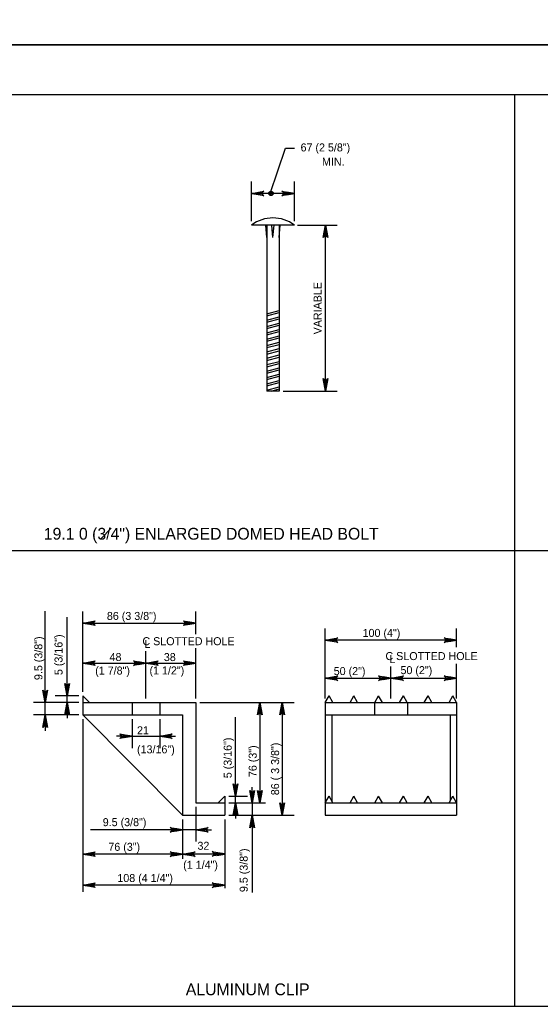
# Model space of a CAD drawing. Extents: x 0 to 36.3, y -66 to 0.
# Drawn here: x 17.21 to 25.01, y -58.48 to -43.62 of the extents above; entities that cross this region are included whole.
import ezdxf

# ---------------------------------------------------------------- set-up
doc = ezdxf.new("R2010")
doc.units = 0
for name, color, linetype in [('1', 7, 'Continuous'), ('3', 7, 'Continuous'), ('4', 7, 'Continuous'), ('5', 7, 'Continuous'), ('63', 7, 'Continuous'), ('8', 7, 'Continuous')]:
    doc.layers.add(name, color=color, linetype=linetype)

msp = doc.modelspace()

# ---------------------------------------------------------------- linework, layer by layer
at = {"layer": '1'}
msp.add_lwpolyline([(1.75, -65.25), (33.25, -65.25), (33.25, -44.75), (1.75, -44.75)], close=True, dxfattribs=at)
at = {"layer": '3'}
for p, q in [((24.625, -58.417), (24.625, -44.75)), ((20.961, -46.229), (21.191, -45.548)), ((21.191, -45.548), (21.325, -45.548)), ((21.369, -46.705), (21.966, -46.705)), ((21.789, -49.193), (21.789, -46.705)), ((21.154, -49.193), (21.966, -49.193)), ((18.423, -51.404), (18.575, -51.252)), ((1.75, -51.583), (32.25, -51.583)), ((21.786, -53.802), (21.786, -52.752)), ((23.754, -53.033), (23.754, -52.752)), ((23.754, -52.929), (21.786, -52.929)), ((21.786, -53.802), (21.786, -53.324)), ((22.77, -53.802), (22.77, -53.324)), ((23.754, -53.802), (23.754, -53.285)), ((23.754, -53.802), (23.754, -53.324)), ((21.786, -53.501), (22.77, -53.501)), ((22.77, -53.501), (23.754, -53.501)), ((18.151, -53.765), (18.25, -53.863)), ((18.151, -53.765), (18.151, -53.863)), ((21.786, -53.863), (21.843, -53.765)), ((21.9, -53.863), (21.843, -53.765)), ((22.157, -53.863), (22.214, -53.765)), ((22.27, -53.863), (22.214, -53.765)), ((22.528, -53.863), (22.585, -53.765)), ((22.642, -53.863), (22.585, -53.765)), ((22.899, -53.863), (22.956, -53.765)), ((23.012, -53.863), (22.956, -53.765)), ((23.27, -53.863), (23.327, -53.765)), ((23.383, -53.863), (23.327, -53.765)), ((23.641, -53.863), (23.698, -53.765)), ((23.754, -53.863), (23.698, -53.765)), ((18.151, -53.863), (19.844, -53.863)), ((18.151, -53.863), (18.151, -54.05)), ((19.844, -53.863), (19.844, -55.369)), ((21.786, -53.863), (21.786, -55.556)), ((21.786, -53.863), (23.754, -53.863)), ((23.754, -53.863), (23.754, -55.556)), ((19.647, -55.556), (18.151, -54.05)), ((21.786, -54.05), (23.754, -54.05)), ((21.884, -54.05), (21.884, -55.343)), ((23.656, -54.05), (23.656, -55.343)), ((18.889, -54.112), (18.889, -54.548)), ((19.303, -54.112), (19.303, -54.548)), ((18.771, -54.371), (18.653, -54.371)), ((18.889, -54.371), (19.303, -54.371)), ((19.421, -54.371), (19.539, -54.371)), ((19.844, -55.369), (20.277, -55.369)), ((20.277, -55.271), (20.179, -55.369)), ((20.277, -55.271), (20.277, -55.369)), ((20.277, -55.369), (20.277, -55.556)), ((21.786, -55.369), (21.843, -55.271)), ((21.786, -55.369), (23.754, -55.369)), ((21.9, -55.369), (21.843, -55.271)), ((22.157, -55.369), (22.214, -55.271)), ((22.27, -55.369), (22.214, -55.271)), ((22.528, -55.369), (22.585, -55.271)), ((22.642, -55.369), (22.585, -55.271)), ((22.899, -55.369), (22.956, -55.271)), ((23.012, -55.369), (22.956, -55.271)), ((23.27, -55.369), (23.327, -55.271)), ((23.383, -55.369), (23.327, -55.271)), ((23.641, -55.369), (23.698, -55.271)), ((23.754, -55.369), (23.698, -55.271)), ((19.647, -55.556), (20.277, -55.556)), ((21.786, -55.556), (23.754, -55.556)), ((1.75, -58.417), (32.25, -58.417))]:
    msp.add_line(p, q, dxfattribs=at)
for points in [[(21.789, -46.705), (21.824, -46.891), (21.814, -46.877), (21.801, -46.869), (21.789, -46.867), (21.776, -46.869), (21.764, -46.877), (21.754, -46.891), (21.789, -46.705), (21.764, -46.877), (21.776, -46.869), (21.789, -46.705), (21.789, -46.867), (21.801, -46.869), (21.789, -46.705), (21.814, -46.877)], [(21.789, -49.193), (21.754, -49.006), (21.764, -49.021), (21.776, -49.028), (21.789, -49.03), (21.801, -49.028), (21.814, -49.021), (21.824, -49.006), (21.789, -49.193), (21.814, -49.021), (21.801, -49.028), (21.789, -49.193), (21.789, -49.03), (21.776, -49.028), (21.789, -49.193), (21.764, -49.021)], [(21.786, -52.929), (21.972, -52.894), (21.958, -52.904), (21.951, -52.916), (21.948, -52.929), (21.951, -52.941), (21.958, -52.954), (21.972, -52.964), (21.786, -52.929), (21.958, -52.954), (21.951, -52.941), (21.786, -52.929), (21.948, -52.929), (21.951, -52.916), (21.786, -52.929), (21.958, -52.904)], [(23.754, -52.929), (23.568, -52.964), (23.582, -52.954), (23.59, -52.941), (23.592, -52.929), (23.59, -52.916), (23.582, -52.904), (23.568, -52.894), (23.754, -52.929), (23.582, -52.904), (23.59, -52.916), (23.754, -52.929), (23.592, -52.929), (23.59, -52.941), (23.754, -52.929), (23.582, -52.954)], [(21.786, -53.501), (21.972, -53.466), (21.958, -53.476), (21.951, -53.488), (21.948, -53.501), (21.951, -53.514), (21.958, -53.526), (21.972, -53.536), (21.786, -53.501), (21.958, -53.526), (21.951, -53.514), (21.786, -53.501), (21.948, -53.501), (21.951, -53.488), (21.786, -53.501), (21.958, -53.476)], [(22.77, -53.501), (22.584, -53.536), (22.598, -53.526), (22.605, -53.514), (22.608, -53.501), (22.605, -53.488), (22.598, -53.476), (22.584, -53.466), (22.77, -53.501), (22.598, -53.476), (22.605, -53.488), (22.77, -53.501), (22.608, -53.501), (22.605, -53.514), (22.77, -53.501), (22.598, -53.526)], [(22.77, -53.501), (22.957, -53.466), (22.942, -53.476), (22.935, -53.488), (22.933, -53.501), (22.935, -53.514), (22.942, -53.526), (22.957, -53.536), (22.77, -53.501), (22.942, -53.526), (22.935, -53.514), (22.77, -53.501), (22.933, -53.501), (22.935, -53.488), (22.77, -53.501), (22.942, -53.476)], [(23.754, -53.501), (23.568, -53.536), (23.582, -53.526), (23.59, -53.514), (23.592, -53.501), (23.59, -53.488), (23.582, -53.476), (23.568, -53.466), (23.754, -53.501), (23.582, -53.476), (23.59, -53.488), (23.754, -53.501), (23.592, -53.501), (23.59, -53.514), (23.754, -53.501), (23.582, -53.526)], [(18.889, -54.371), (18.703, -54.406), (18.717, -54.396), (18.725, -54.384), (18.727, -54.371), (18.725, -54.359), (18.717, -54.346), (18.703, -54.336), (18.889, -54.371), (18.717, -54.346), (18.725, -54.359), (18.889, -54.371), (18.727, -54.371), (18.725, -54.384), (18.889, -54.371), (18.717, -54.396)], [(19.303, -54.371), (19.489, -54.336), (19.475, -54.346), (19.467, -54.359), (19.465, -54.371), (19.467, -54.384), (19.475, -54.396), (19.489, -54.406), (19.303, -54.371), (19.475, -54.396), (19.467, -54.384), (19.303, -54.371), (19.465, -54.371), (19.467, -54.359), (19.303, -54.371), (19.475, -54.346)]]:
    msp.add_lwpolyline(points, dxfattribs=at)
for points in [[(21.808, -46.823), (21.769, -46.823), (21.789, -46.705)], [(21.808, -49.075), (21.769, -49.075), (21.789, -49.193)], [(21.904, -52.909), (21.904, -52.948), (21.786, -52.929)], [(23.636, -52.909), (23.636, -52.948), (23.754, -52.929)], [(21.904, -53.481), (21.904, -53.521), (21.786, -53.501)], [(22.652, -53.481), (22.652, -53.521), (22.77, -53.501)], [(22.888, -53.481), (22.888, -53.521), (22.77, -53.501)], [(23.636, -53.481), (23.636, -53.521), (23.754, -53.501)], [(18.771, -54.352), (18.771, -54.391), (18.889, -54.371)], [(19.421, -54.352), (19.421, -54.391), (19.303, -54.371)]]:
    msp.add_lwpolyline(points, close=True, dxfattribs=at)
for radius in [0.0333, 0.0167]:
    msp.add_circle((20.972, -46.229), radius, dxfattribs=at)
at = {"layer": '4'}
for p, q in [((20.678, -46.643), (20.678, -46.051)), ((21.323, -46.643), (21.323, -46.051)), ((21.205, -46.229), (20.796, -46.229)), ((21.323, -46.705), (20.678, -46.705)), ((20.908, -46.889), (20.892, -46.705)), ((20.908, -46.705), (20.908, -49.193)), ((21, -46.889), (20.984, -46.705)), ((21, -46.889), (21.017, -46.705)), ((21.093, -46.705), (21.093, -49.193)), ((21.093, -46.889), (21.109, -46.705)), ((21.093, -49.193), (20.908, -49.193)), ((21.093, -49.193), (21.093, -49.193)), ((17.588, -53.745), (17.588, -52.495)), ((18.151, -53.703), (18.151, -52.497)), ((19.844, -52.841), (19.844, -52.497)), ((17.914, -53.647), (17.914, -52.584)), ((18.269, -52.674), (19.726, -52.674)), ((18.151, -53.703), (18.151, -53.096)), ((19.096, -53.802), (19.096, -53.096)), ((19.844, -53.802), (19.844, -53.05)), ((19.844, -53.802), (19.844, -53.096)), ((18.269, -53.273), (18.978, -53.273)), ((19.214, -53.273), (19.726, -53.273)), ((18.09, -53.765), (17.737, -53.765)), ((17.914, -53.863), (17.914, -53.765)), ((18.09, -53.863), (17.411, -53.863)), ((17.588, -54.05), (17.588, -53.863)), ((18.09, -53.863), (17.733, -53.863)), ((18.09, -53.863), (17.737, -53.863)), ((19.905, -53.863), (21.318, -53.863)), ((19.905, -53.863), (20.982, -53.863)), ((20.805, -53.863), (20.805, -55.251)), ((21.141, -53.863), (21.141, -55.438)), ((18.09, -54.05), (17.411, -54.05)), ((17.914, -53.981), (17.914, -54.1)), ((17.588, -54.169), (17.588, -54.287)), ((18.151, -54.112), (18.151, -56.446)), ((18.151, -54.112), (18.151, -56.703)), ((20.439, -55.153), (20.439, -54.082)), ((20.691, -55.251), (20.691, -55.133)), ((20.339, -55.271), (20.617, -55.271)), ((20.339, -55.369), (20.617, -55.369)), ((20.339, -55.369), (20.868, -55.369)), ((20.339, -55.369), (20.887, -55.369)), ((20.439, -55.369), (20.439, -55.271)), ((20.691, -55.369), (20.691, -55.556)), ((19.844, -55.431), (19.844, -55.949)), ((20.439, -55.487), (20.439, -55.605)), ((19.647, -55.618), (19.647, -56.209)), ((19.647, -55.679), (19.647, -55.949)), ((20.277, -55.618), (20.277, -56.446)), ((20.277, -55.618), (20.277, -56.651)), ((20.339, -55.556), (20.868, -55.556)), ((20.339, -55.556), (20.375, -55.556)), ((20.546, -55.556), (21.318, -55.556)), ((20.691, -55.674), (20.691, -56.713)), ((19.529, -55.772), (18.266, -55.772)), ((19.844, -55.772), (19.647, -55.772)), ((19.962, -55.772), (20.08, -55.772)), ((19.529, -56.137), (18.269, -56.137)), ((20.159, -56.137), (19.765, -56.137)), ((20.159, -56.605), (18.269, -56.605))]:
    msp.add_line(p, q, dxfattribs=at)
for points in [[(20.678, -46.229), (20.865, -46.194), (20.85, -46.204), (20.843, -46.216), (20.841, -46.229), (20.843, -46.241), (20.85, -46.254), (20.865, -46.264), (20.678, -46.229), (20.85, -46.254), (20.843, -46.241), (20.678, -46.229), (20.841, -46.229), (20.843, -46.216), (20.678, -46.229), (20.85, -46.204)], [(21.323, -46.229), (21.136, -46.264), (21.151, -46.254), (21.158, -46.241), (21.16, -46.229), (21.158, -46.216), (21.151, -46.204), (21.136, -46.194), (21.323, -46.229), (21.151, -46.204), (21.158, -46.216), (21.323, -46.229), (21.16, -46.229), (21.158, -46.241), (21.323, -46.229), (21.151, -46.254)], [(18.151, -52.674), (18.337, -52.639), (18.323, -52.649), (18.316, -52.661), (18.314, -52.674), (18.316, -52.686), (18.323, -52.699), (18.337, -52.709), (18.151, -52.674), (18.323, -52.699), (18.316, -52.686), (18.151, -52.674), (18.314, -52.674), (18.316, -52.661), (18.151, -52.674), (18.323, -52.649)], [(19.844, -52.674), (19.658, -52.709), (19.672, -52.699), (19.679, -52.686), (19.681, -52.674), (19.679, -52.661), (19.672, -52.649), (19.658, -52.639), (19.844, -52.674), (19.672, -52.649), (19.679, -52.661), (19.844, -52.674), (19.681, -52.674), (19.679, -52.686), (19.844, -52.674), (19.672, -52.699)], [(18.151, -53.273), (18.337, -53.238), (18.323, -53.248), (18.316, -53.261), (18.314, -53.273), (18.316, -53.286), (18.323, -53.298), (18.337, -53.308), (18.151, -53.273), (18.323, -53.298), (18.316, -53.286), (18.151, -53.273), (18.314, -53.273), (18.316, -53.261), (18.151, -53.273), (18.323, -53.248)], [(19.096, -53.273), (18.91, -53.308), (18.924, -53.298), (18.931, -53.286), (18.933, -53.273), (18.931, -53.261), (18.924, -53.248), (18.91, -53.238), (19.096, -53.273), (18.924, -53.248), (18.931, -53.261), (19.096, -53.273), (18.933, -53.273), (18.931, -53.286), (19.096, -53.273), (18.924, -53.298)], [(19.096, -53.273), (19.282, -53.238), (19.268, -53.248), (19.261, -53.261), (19.258, -53.273), (19.261, -53.286), (19.268, -53.298), (19.282, -53.308), (19.096, -53.273), (19.268, -53.298), (19.261, -53.286), (19.096, -53.273), (19.258, -53.273), (19.261, -53.261), (19.096, -53.273), (19.268, -53.248)], [(19.844, -53.273), (19.658, -53.308), (19.672, -53.298), (19.679, -53.286), (19.681, -53.273), (19.679, -53.261), (19.672, -53.248), (19.658, -53.238), (19.844, -53.273), (19.672, -53.248), (19.679, -53.261), (19.844, -53.273), (19.681, -53.273), (19.679, -53.286), (19.844, -53.273), (19.672, -53.298)], [(17.914, -53.765), (17.879, -53.579), (17.889, -53.593), (17.902, -53.6), (17.914, -53.602), (17.927, -53.6), (17.939, -53.593), (17.949, -53.579), (17.914, -53.765), (17.939, -53.593), (17.927, -53.6), (17.914, -53.765), (17.914, -53.602), (17.902, -53.6), (17.914, -53.765), (17.889, -53.593)], [(17.588, -53.863), (17.553, -53.677), (17.563, -53.691), (17.576, -53.699), (17.588, -53.701), (17.601, -53.699), (17.613, -53.691), (17.623, -53.677), (17.588, -53.863), (17.613, -53.691), (17.601, -53.699), (17.588, -53.863), (17.588, -53.701), (17.576, -53.699), (17.588, -53.863), (17.563, -53.691)], [(17.914, -53.863), (17.949, -54.05), (17.939, -54.035), (17.927, -54.028), (17.914, -54.026), (17.902, -54.028), (17.889, -54.035), (17.879, -54.05), (17.914, -53.863), (17.889, -54.035), (17.902, -54.028), (17.914, -53.863), (17.914, -54.026), (17.927, -54.028), (17.914, -53.863), (17.939, -54.035)], [(20.805, -53.863), (20.84, -54.05), (20.83, -54.035), (20.817, -54.028), (20.805, -54.026), (20.793, -54.028), (20.78, -54.035), (20.77, -54.05), (20.805, -53.863), (20.78, -54.035), (20.793, -54.028), (20.805, -53.863), (20.805, -54.026), (20.817, -54.028), (20.805, -53.863), (20.83, -54.035)], [(21.141, -53.863), (21.176, -54.05), (21.166, -54.035), (21.154, -54.028), (21.141, -54.026), (21.129, -54.028), (21.116, -54.035), (21.106, -54.05), (21.141, -53.863), (21.116, -54.035), (21.129, -54.028), (21.141, -53.863), (21.141, -54.026), (21.154, -54.028), (21.141, -53.863), (21.166, -54.035)], [(17.588, -54.05), (17.623, -54.237), (17.613, -54.222), (17.601, -54.215), (17.588, -54.213), (17.576, -54.215), (17.563, -54.222), (17.553, -54.237), (17.588, -54.05), (17.563, -54.222), (17.576, -54.215), (17.588, -54.05), (17.588, -54.213), (17.601, -54.215), (17.588, -54.05), (17.613, -54.222)], [(20.439, -55.271), (20.404, -55.084), (20.414, -55.099), (20.427, -55.106), (20.439, -55.108), (20.452, -55.106), (20.464, -55.099), (20.474, -55.084), (20.439, -55.271), (20.464, -55.099), (20.452, -55.106), (20.439, -55.271), (20.439, -55.108), (20.427, -55.106), (20.439, -55.271), (20.414, -55.099)], [(20.691, -55.369), (20.656, -55.183), (20.666, -55.197), (20.678, -55.205), (20.691, -55.207), (20.703, -55.205), (20.716, -55.197), (20.726, -55.183), (20.691, -55.369), (20.716, -55.197), (20.703, -55.205), (20.691, -55.369), (20.691, -55.207), (20.678, -55.205), (20.691, -55.369), (20.666, -55.197)], [(20.805, -55.369), (20.77, -55.183), (20.78, -55.197), (20.793, -55.205), (20.805, -55.207), (20.817, -55.205), (20.83, -55.197), (20.84, -55.183), (20.805, -55.369), (20.83, -55.197), (20.817, -55.205), (20.805, -55.369), (20.805, -55.207), (20.793, -55.205), (20.805, -55.369), (20.78, -55.197)], [(20.439, -55.369), (20.474, -55.556), (20.464, -55.541), (20.452, -55.534), (20.439, -55.532), (20.427, -55.534), (20.414, -55.541), (20.404, -55.556), (20.439, -55.369), (20.414, -55.541), (20.427, -55.534), (20.439, -55.369), (20.439, -55.532), (20.452, -55.534), (20.439, -55.369), (20.464, -55.541)], [(21.141, -55.556), (21.106, -55.37), (21.116, -55.384), (21.129, -55.392), (21.141, -55.394), (21.154, -55.392), (21.166, -55.384), (21.176, -55.37), (21.141, -55.556), (21.166, -55.384), (21.154, -55.392), (21.141, -55.556), (21.141, -55.394), (21.129, -55.392), (21.141, -55.556), (21.116, -55.384)], [(20.691, -55.556), (20.726, -55.743), (20.716, -55.728), (20.703, -55.721), (20.691, -55.719), (20.678, -55.721), (20.666, -55.728), (20.656, -55.743), (20.691, -55.556), (20.666, -55.728), (20.678, -55.721), (20.691, -55.556), (20.691, -55.719), (20.703, -55.721), (20.691, -55.556), (20.716, -55.728)], [(19.647, -55.772), (19.461, -55.807), (19.475, -55.797), (19.482, -55.785), (19.485, -55.772), (19.482, -55.76), (19.475, -55.747), (19.461, -55.737), (19.647, -55.772), (19.475, -55.747), (19.482, -55.76), (19.647, -55.772), (19.485, -55.772), (19.482, -55.785), (19.647, -55.772), (19.475, -55.797)], [(19.844, -55.772), (20.03, -55.737), (20.016, -55.747), (20.009, -55.76), (20.006, -55.772), (20.009, -55.785), (20.016, -55.797), (20.03, -55.807), (19.844, -55.772), (20.016, -55.797), (20.009, -55.785), (19.844, -55.772), (20.006, -55.772), (20.009, -55.76), (19.844, -55.772), (20.016, -55.747)], [(18.151, -56.137), (18.337, -56.102), (18.323, -56.112), (18.316, -56.125), (18.314, -56.137), (18.316, -56.15), (18.323, -56.162), (18.337, -56.172), (18.151, -56.137), (18.323, -56.162), (18.316, -56.15), (18.151, -56.137), (18.314, -56.137), (18.316, -56.125), (18.151, -56.137), (18.323, -56.112)], [(19.647, -56.137), (19.461, -56.172), (19.475, -56.162), (19.482, -56.15), (19.485, -56.137), (19.482, -56.125), (19.475, -56.112), (19.461, -56.102), (19.647, -56.137), (19.475, -56.112), (19.482, -56.125), (19.647, -56.137), (19.485, -56.137), (19.482, -56.15), (19.647, -56.137), (19.475, -56.162)], [(19.647, -56.137), (19.834, -56.102), (19.819, -56.112), (19.812, -56.125), (19.81, -56.137), (19.812, -56.15), (19.819, -56.162), (19.834, -56.172), (19.647, -56.137), (19.819, -56.162), (19.812, -56.15), (19.647, -56.137), (19.81, -56.137), (19.812, -56.125), (19.647, -56.137), (19.819, -56.112)], [(20.277, -56.136), (20.091, -56.171), (20.105, -56.161), (20.112, -56.149), (20.115, -56.136), (20.112, -56.124), (20.105, -56.111), (20.091, -56.101), (20.277, -56.136), (20.105, -56.111), (20.112, -56.124), (20.277, -56.136), (20.115, -56.136), (20.112, -56.149), (20.277, -56.136), (20.105, -56.161)], [(18.151, -56.605), (18.337, -56.57), (18.323, -56.58), (18.316, -56.593), (18.314, -56.605), (18.316, -56.618), (18.323, -56.63), (18.337, -56.64), (18.151, -56.605), (18.323, -56.63), (18.316, -56.618), (18.151, -56.605), (18.314, -56.605), (18.316, -56.593), (18.151, -56.605), (18.323, -56.58)], [(20.277, -56.605), (20.091, -56.64), (20.105, -56.63), (20.112, -56.618), (20.115, -56.605), (20.112, -56.593), (20.105, -56.58), (20.091, -56.57), (20.277, -56.605), (20.105, -56.58), (20.112, -56.593), (20.277, -56.605), (20.115, -56.605), (20.112, -56.618), (20.277, -56.605), (20.105, -56.63)]]:
    msp.add_lwpolyline(points, dxfattribs=at)
for points in [[(20.796, -46.209), (20.796, -46.248), (20.678, -46.229)], [(21.205, -46.209), (21.205, -46.248), (21.323, -46.229)], [(18.269, -52.654), (18.269, -52.694), (18.151, -52.674)], [(19.726, -52.654), (19.726, -52.694), (19.844, -52.674)], [(18.269, -53.253), (18.269, -53.293), (18.151, -53.273)], [(18.978, -53.253), (18.978, -53.293), (19.096, -53.273)], [(19.214, -53.253), (19.214, -53.293), (19.096, -53.273)], [(19.726, -53.253), (19.726, -53.293), (19.844, -53.273)], [(17.569, -53.745), (17.608, -53.745), (17.588, -53.863)], [(17.895, -53.647), (17.934, -53.647), (17.914, -53.765)], [(17.895, -53.981), (17.934, -53.981), (17.914, -53.863)], [(20.785, -53.981), (20.825, -53.981), (20.805, -53.863)], [(21.122, -53.981), (21.161, -53.981), (21.141, -53.863)], [(17.569, -54.169), (17.608, -54.169), (17.588, -54.05)], [(20.42, -55.153), (20.459, -55.153), (20.439, -55.271)], [(20.671, -55.251), (20.71, -55.251), (20.691, -55.369)], [(20.785, -55.251), (20.825, -55.251), (20.805, -55.369)], [(20.42, -55.487), (20.459, -55.487), (20.439, -55.369)], [(21.122, -55.438), (21.161, -55.438), (21.141, -55.556)], [(20.671, -55.674), (20.71, -55.674), (20.691, -55.556)], [(19.529, -55.752), (19.529, -55.792), (19.647, -55.772)], [(19.962, -55.752), (19.962, -55.792), (19.844, -55.772)], [(18.269, -56.118), (18.269, -56.157), (18.151, -56.137)], [(19.529, -56.118), (19.529, -56.157), (19.647, -56.137)], [(19.765, -56.118), (19.765, -56.157), (19.647, -56.137)], [(20.159, -56.118), (20.159, -56.157), (20.277, -56.137)], [(18.269, -56.586), (18.269, -56.625), (18.151, -56.605)], [(20.159, -56.586), (20.159, -56.625), (20.277, -56.605)]]:
    msp.add_lwpolyline(points, close=True, dxfattribs=at)
msp.add_arc((21, -47.135), 0.538, 53.1817, 126.8184, dxfattribs=at)
at = {"layer": '5'}
for p, q in [((20.908, -48.033), (21.093, -47.983)), ((20.908, -48.065), (21.093, -48.015)), ((20.908, -48.128), (21.093, -48.079)), ((20.908, -48.16), (21.093, -48.111)), ((20.908, -48.224), (21.093, -48.175)), ((20.908, -48.256), (21.093, -48.206)), ((20.908, -48.319), (21.093, -48.27)), ((20.908, -48.351), (21.093, -48.302)), ((20.908, -48.415), (21.093, -48.366)), ((20.908, -48.447), (21.093, -48.397)), ((20.908, -48.511), (21.093, -48.461)), ((20.908, -48.542), (21.093, -48.493)), ((20.908, -48.606), (21.093, -48.557)), ((20.908, -48.638), (21.093, -48.588)), ((20.908, -48.702), (21.093, -48.652)), ((20.908, -48.733), (21.093, -48.684)), ((20.908, -48.797), (21.093, -48.748)), ((20.908, -48.829), (21.093, -48.779)), ((20.908, -48.893), (21.093, -48.843)), ((20.908, -48.925), (21.093, -48.875)), ((20.908, -48.988), (21.093, -48.939)), ((20.908, -49.02), (21.093, -48.971)), ((20.908, -49.084), (21.093, -49.034)), ((20.908, -49.116), (21.093, -49.066)), ((20.908, -49.179), (21.093, -49.13)), ((20.976, -49.193), (21.093, -49.162))]:
    msp.add_line(p, q, dxfattribs=at)
at = {"layer": '63'}
for points in [[(0, -44), (34, -44), (34, -22), (0, -22)], [(0, -66), (34, -66), (34, -44), (0, -44)]]:
    msp.add_lwpolyline(points, close=True, dxfattribs=at)
at = {"layer": '8'}
for p, q in [((18.889, -53.863), (18.889, -54.05)), ((19.303, -53.863), (19.303, -54.05)), ((22.524, -53.863), (22.524, -54.05)), ((23.016, -53.863), (23.016, -54.05)), ((18.151, -54.05), (19.647, -54.05)), ((19.647, -54.05), (19.647, -55.556))]:
    msp.add_line(p, q, dxfattribs=at)

# ---------------------------------------------------------------- texts
at = {"layer": '3'}
msp.add_text('VARIABLE', height=0.12, rotation=90, dxfattribs=at).set_placement((21.73, -48.343))
for s, height, p in [('19.1 0 (3/4") ENLARGED DOMED HEAD BOLT', 0.17717, (17.565, -51.422)), ('100 (4")', 0.12, (22.345, -52.881)), ('C SLOTTED HOLE', 0.12, (19.044, -53.005)), ('C SLOTTED HOLE', 0.12, (22.688, -53.228)), ('50 (2")', 0.12, (21.912, -53.453)), ('50 (2")', 0.12, (22.913, -53.439)), ('21', 0.12, (18.963, -54.341)), ('(13/16")', 0.12, (18.963, -54.627)), ('ALUMINUM CLIP', 0.17717, (19.694, -58.255))]:
    msp.add_text(s, height=height, dxfattribs=at).set_placement(p)
at = {"layer": '4'}
for s, p in [('67 (2 5/8")', (21.415, -45.599)), ('MIN.', (21.736, -45.812)), ('86 (3 3/8")', (18.511, -52.626)), ('L', (19.074, -53.046)), ('48', (18.551, -53.242)), ('38', (19.365, -53.243)), ('L', (22.748, -53.274)), ('(1 7/8")', (18.336, -53.445)), ('(1 1/2")', (19.15, -53.443)), ('9.5 (3/8")', (18.449, -55.719)), ('76 (3")', (18.533, -56.089)), ('32', (19.869, -56.073)), ('(1 1/4")', (19.655, -56.359)), ('108 (4 1/4")', (18.668, -56.557))]:
    msp.add_text(s, height=0.12, dxfattribs=at).set_placement(p)
for s, p in [('5 (3/16")', (17.846, -53.453)), ('9.5 (3/8")', (17.544, -53.528)), ('5 (3/16")', (20.382, -55)), ('86 ( 3 3/8")', (21.093, -55.255)), ('76 (3")', (20.757, -54.983)), ('9.5 (3/8")', (20.622, -56.708))]:
    msp.add_text(s, height=0.12, rotation=90, dxfattribs=at).set_placement(p)

doc.saveas('drawing.dxf')
